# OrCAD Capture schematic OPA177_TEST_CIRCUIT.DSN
size A; title: OPA177: Precision Operational Amplifier; rev: 1.0; note: Datasheet: SBOS008  EVM: N/A
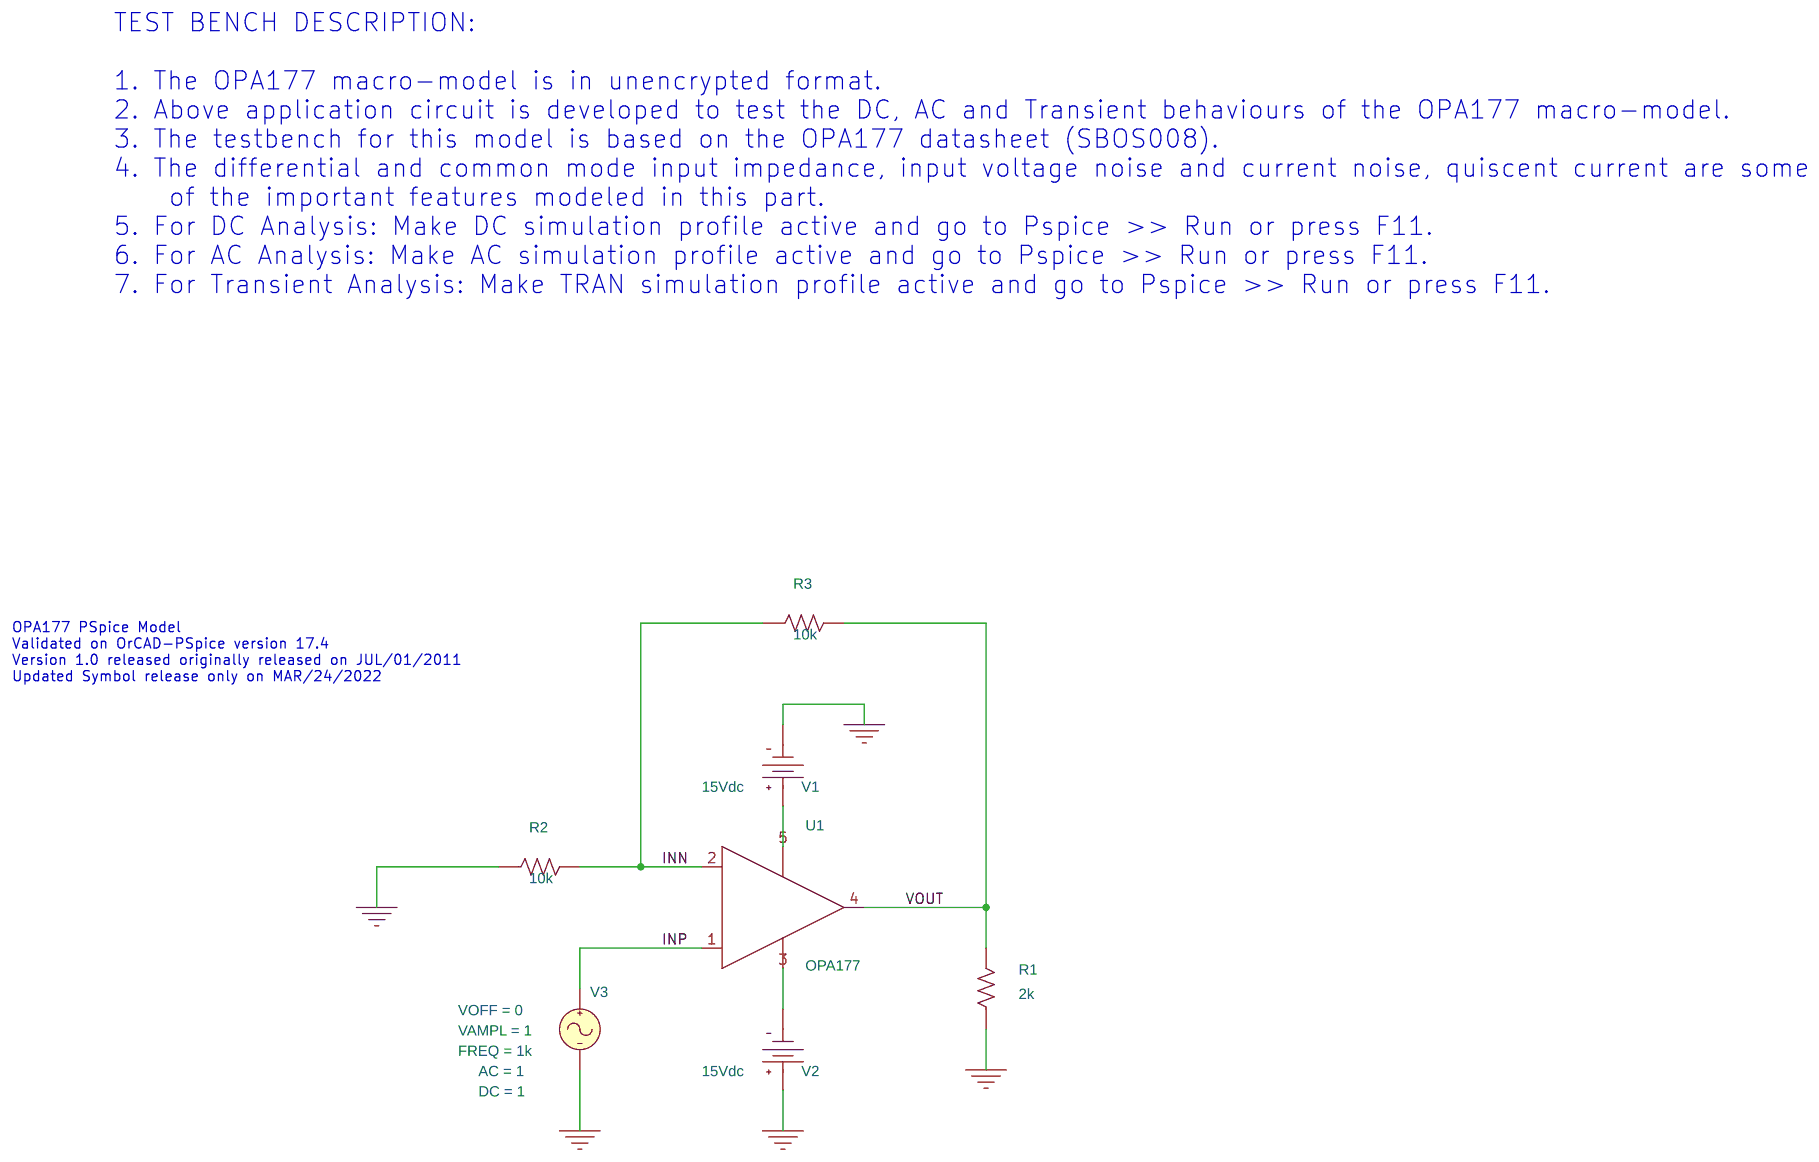
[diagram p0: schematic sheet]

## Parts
R1  2k  [AXRC05]
R2  10k  [AXRC05]
R3  10k  [AXRC05]
U1  OPA177
V1  VDC
V2  VDC
V3  VSIN

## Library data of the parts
R1-R3 = R
U1 = OPA177
V1 V2 = VDC: DC: 15Vdc
V3 = VSIN: AC: 1; DC: 1; FREQ: 1k; VAMPL: 1; VOFF: 0

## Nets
0: R1.1 R2.1 V1.1(-) V2.0(+) V3.2(-)
INN: R2.2 R3.1 U1.2(-)
INP: U1.1(+) V3.1(+)
VOUT: R1.2 R3.2 U1.4(OUT)
N00125: U1.3(V-) V2.1(-)
N00129: U1.5(V+) V1.0(+)

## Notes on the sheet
- TEST BENCH DESCRIPTION:
  1. The OPA177 macro-model is in unencrypted format.
  2. Above application circuit is developed to test the DC, AC and Transient behaviours of the OPA177 macro-model.
  3. The testbench for this model is based on the OPA177 datasheet (SBOS008).
  4. The differential and common mode input impedance, input voltage noise and current noise, quiscent current are some
      of the important features modeled in this part.
  5. For DC Analysis: Make DC simulation profile active and go to Pspice >> Run or press F11.
  6. For AC Analysis: Make AC simulation profile active and go to Pspice >> Run or press F11.
  7. For Transient Analysis: Make TRAN simulation profile active and go to Pspice >> Run or press F11.
- OPA177 PSpice Model
  Validated on OrCAD-PSpice version 17.4
  Version 1.0 released originally released on JUL/01/2011
  Updated Symbol release only on MAR/24/2022
